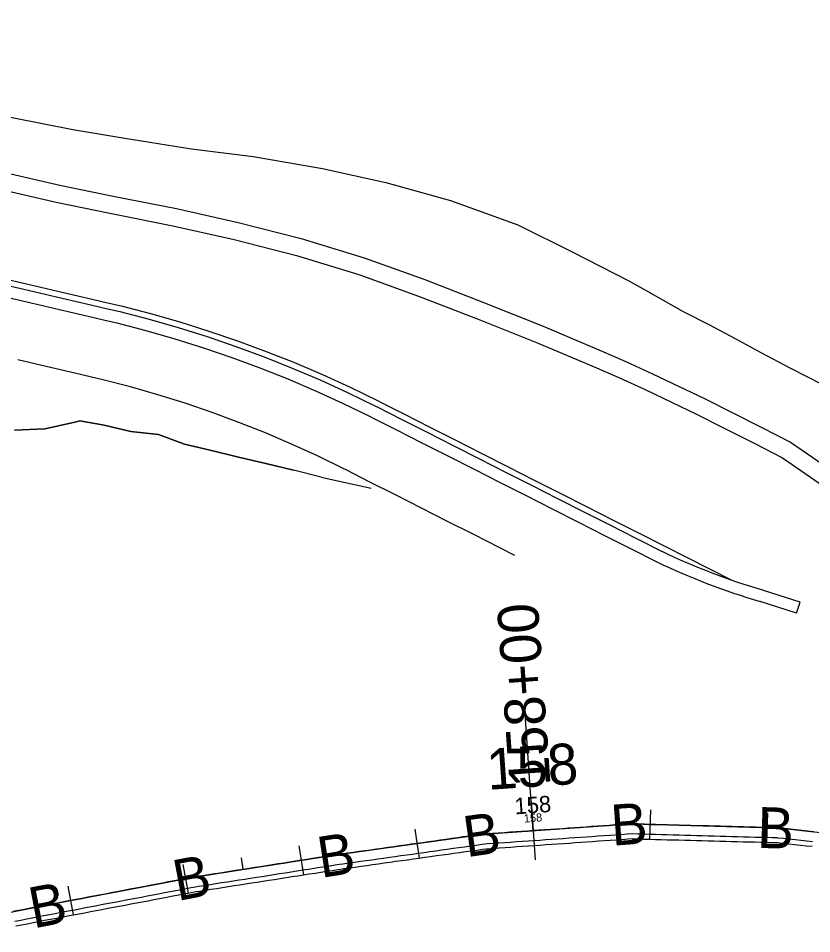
# Model space of a CAD drawing. Extents: x 1823824 to 1861612, y 706975 to 726130.
# Drawn here: x 1825664.3 to 1825799.9, y 715514.9 to 715671.4 of the extents above; entities that cross this region are included whole.
import ezdxf

# ---------------------------------------------------------------- set-up
doc = ezdxf.new("R2010")
doc.units = 0
for name, color, linetype in [('DR_X_Flood_Boundary', 7, 'Continuous'), ('GE_X_CL_10', 7, 'Continuous'), ('GE_X_CL_100', 7, 'Continuous'), ('GE_X_CL_20', 7, 'Continuous'), ('GE_X_CL_200', 7, 'Continuous'), ('GE_X_CL_50', 7, 'Continuous'), ('SC_Scratch1', 7, 'Continuous'), ('SC_Scratch3', 7, 'Continuous'), ('SC_Scratch5', 7, 'Continuous'), ('SC_Scratch6', 7, 'Continuous')]:
    doc.layers.add(name, color=color, linetype=linetype)

msp = doc.modelspace()

# ---------------------------------------------------------------- linework, layer by layer
at = {"layer": 'DR_X_Flood_Boundary'}
for p, q in [((1825743.89, 715531.89), (1825769.06, 715533.64)), ((1825769.06, 715533.64), (1825794.14, 715532.96)), ((1825794.14, 715532.96), (1825817.43, 715530.38)), ((1825718.99, 715528.4), (1825743.89, 715531.89)), ((1825694.33, 715524.53), (1825718.99, 715528.4)), ((1825669.7, 715519.85), (1825694.33, 715524.53)), ((1825643.98, 715514.87), (1825669.7, 715519.85))]:
    msp.add_line(p, q, dxfattribs=at)
at = {"layer": 'GE_X_CL_10'}
for p, q in [((1825752.33, 715532.48), (1825752.26, 715533.47)), ((1825702.79, 715525.86), (1825702.63, 715526.85))]:
    msp.add_line(p, q, dxfattribs=at)
at = {"layer": 'GE_X_CL_100'}
msp.add_line((1825752.33, 715532.48), (1825751.63, 715542.45), dxfattribs=at)
at = {"layer": 'GE_X_CL_20'}
for p, q in [((1825752.33, 715532.48), (1825752.19, 715534.47)), ((1825702.79, 715525.86), (1825702.48, 715527.83))]:
    msp.add_line(p, q, dxfattribs=at)
at = {"layer": 'GE_X_CL_200'}
msp.add_line((1825752.33, 715532.48), (1825750.94, 715552.43), dxfattribs=at)
at = {"layer": 'GE_X_CL_50'}
msp.add_line((1825752.33, 715532.48), (1825751.98, 715537.47), dxfattribs=at)
at = {"layer": 'SC_Scratch1'}
for p, q in [((1825796.3, 715598.91), (1825796.48, 715598.82)), ((1825716.1, 715592.93), (1825724.66, 715591.03)), ((1825774.79, 715581.13), (1825786.13, 715575.37)), ((1825797.93, 715571.57), (1825791.7, 715573.57)), ((1825797.32, 715569.67), (1825791.09, 715571.67)), ((1825797.32, 715569.67), (1825797.93, 715571.57))]:
    msp.add_line(p, q, dxfattribs=at)
for points in [[(1825528.59, 715668.86), (1825540.4, 715670.37), (1825553.63, 715671.36), (1825566.19, 715671.39), (1825577.99, 715670.57), (1825589.44, 715668.99), (1825601.17, 715667.57), (1825612.54, 715665.75), (1825623.77, 715663.16), (1825633.92, 715660.63), (1825643.99, 715658.43), (1825653.89, 715656.38), (1825663.57, 715654.39), (1825673.68, 715652.35), (1825682.56, 715650.87), (1825693.93, 715649.06), (1825704.45, 715647.73), (1825716.32, 715645.7), (1825727.12, 715643.32), (1825738.2, 715640.21), (1825749.67, 715636.1), (1825759.12, 715631.42), (1825768.57, 715626.56), (1825771.61, 715624.85)], [(1825661.6, 715645.14), (1825671.44, 715642.87), (1825680.58, 715640.99), (1825691.37, 715638.84), (1825701.9, 715636.48), (1825712.69, 715633.72), (1825723.46, 715630.42), (1825733.79, 715626.7), (1825744, 715622.72), (1825754.05, 715618.72), (1825763.54, 715614.73), (1825766.46, 715613.43)], [(1825660.92, 715642.22), (1825670.8, 715639.94), (1825679.98, 715638.05), (1825690.75, 715635.9), (1825701.2, 715633.56), (1825711.87, 715630.83), (1825722.52, 715627.58), (1825732.74, 715623.9), (1825742.9, 715619.93), (1825752.91, 715615.95), (1825762.34, 715611.98), (1825765.24, 715610.69)], [(1825662.34, 715626.79), (1825667.21, 715625.65), (1825672.08, 715624.51), (1825676.95, 715623.38), (1825679.6, 715622.75), (1825681.9, 715622.2), (1825686.94, 715620.9), (1825691.94, 715619.47), (1825696.9, 715617.91), (1825701.82, 715616.23), (1825706.7, 715614.43), (1825711.53, 715612.51), (1825716.31, 715610.47), (1825721.04, 715608.31), (1825725.71, 715606.03), (1825726.33, 715605.71), (1825730.2, 715603.75), (1825734.66, 715601.49), (1825739.11, 715599.23), (1825743.57, 715596.97), (1825748.03, 715594.7), (1825752.49, 715592.44), (1825756.95, 715590.18), (1825761.41, 715587.92), (1825765.87, 715585.65), (1825770.33, 715583.39), (1825774.79, 715581.13)], [(1825662.12, 715625.82), (1825666.98, 715624.68), (1825671.85, 715623.54), (1825676.72, 715622.4), (1825679.38, 715621.78), (1825681.67, 715621.23), (1825686.68, 715619.93), (1825691.65, 715618.51), (1825696.59, 715616.96), (1825701.49, 715615.29), (1825706.34, 715613.5), (1825711.15, 715611.58), (1825715.91, 715609.55), (1825720.62, 715607.4), (1825725.26, 715605.13), (1825725.88, 715604.82), (1825729.75, 715602.86), (1825734.21, 715600.6), (1825738.66, 715598.33), (1825743.12, 715596.07), (1825747.58, 715593.81), (1825752.04, 715591.55), (1825756.5, 715589.28), (1825760.96, 715587.02), (1825765.41, 715584.76), (1825769.87, 715582.5), (1825774.33, 715580.24)], [(1825771.61, 715624.85), (1825777.97, 715621.23), (1825782.31, 715619.01), (1825786.84, 715616.63), (1825791.22, 715614.26), (1825796.17, 715611.62), (1825801.88, 715608.7)], [(1825661.66, 715623.87), (1825666.53, 715622.73), (1825671.4, 715621.59), (1825676.27, 715620.45), (1825678.92, 715619.83), (1825681.19, 715619.29), (1825686.15, 715618), (1825691.07, 715616.59), (1825695.96, 715615.06), (1825700.82, 715613.41), (1825705.62, 715611.63), (1825710.38, 715609.74), (1825715.1, 715607.72), (1825719.76, 715605.59), (1825724.36, 715603.35), (1825724.98, 715603.04), (1825728.84, 715601.08), (1825733.3, 715598.82), (1825737.76, 715596.55), (1825742.22, 715594.29), (1825746.67, 715592.03), (1825751.13, 715589.77), (1825755.59, 715587.5), (1825760.05, 715585.24), (1825764.51, 715582.98), (1825768.97, 715580.72), (1825773.43, 715578.45)], [(1825749.19, 715579.54), (1825746.61, 715580.85), (1825742.15, 715583.11), (1825737.69, 715585.37), (1825733.23, 715587.64), (1825728.77, 715589.9), (1825724.31, 715592.16), (1825720.45, 715594.12), (1825719.87, 715594.41), (1825715.49, 715596.55), (1825711.05, 715598.58), (1825706.57, 715600.49), (1825702.04, 715602.29), (1825697.47, 715603.98), (1825692.85, 715605.56), (1825688.2, 715607.01), (1825683.52, 715608.36), (1825678.8, 715609.58), (1825676.64, 715610.1), (1825673.99, 715610.72), (1825669.12, 715611.86), (1825664.25, 715613)], [(1825766.46, 715613.43), (1825768.28, 715612.63), (1825772.7, 715610.62), (1825777.27, 715608.46), (1825781.58, 715606.36), (1825786.18, 715604.05), (1825791.41, 715601.4), (1825796.3, 715598.91)], [(1825765.24, 715610.69), (1825767.05, 715609.89), (1825771.44, 715607.9), (1825775.97, 715605.75), (1825780.25, 715603.68), (1825784.83, 715601.38), (1825790.05, 715598.72), (1825794.94, 715596.24)], [(1825663.69, 715600.98), (1825668.87, 715601.18), (1825674.29, 715602.39), (1825674.88, 715602.54), (1825679, 715601.83), (1825683.57, 715600.75), (1825688.32, 715600.2), (1825692.74, 715598.57), (1825697.35, 715597.47), (1825701.99, 715596.37), (1825706.66, 715595.25), (1825711.37, 715594.13)], [(1825716.1, 715592.93), (1825711.37, 715594.13), (1825706.66, 715595.25), (1825701.99, 715596.37), (1825697.35, 715597.47), (1825692.74, 715598.57), (1825688.32, 715600.2), (1825683.57, 715600.75), (1825679, 715601.83), (1825674.88, 715602.54), (1825674.29, 715602.39), (1825668.87, 715601.18), (1825663.69, 715600.98)], [(1825796.48, 715598.82), (1825811.61, 715588.35), (1825827.84, 715576.05)], [(1825794.94, 715596.24), (1825809.85, 715585.92), (1825826.03, 715573.66)]]:
    msp.add_lwpolyline(points, dxfattribs=at)
for centre, radius, start, end in [((1825785.13, 715575.88), 25.6, 64.1366, 64.2815), ((1825824.98, 715686.31), 117.54, 244.451, 253.5296), ((1825824.98, 715686.31), 119.54, 244.451, 253.5296)]:
    msp.add_arc(centre, radius, start, end, dxfattribs=at)
at = {"layer": 'SC_Scratch3'}
for points in [[(1825800.24, 715532.29), (1825799.25, 715532.4), (1825798.25, 715532.51), (1825797.26, 715532.62), (1825796.27, 715532.73), (1825795.27, 715532.84), (1825794.28, 715532.95), (1825794.14, 715532.97), (1825793.28, 715532.99), (1825792.28, 715533.02), (1825791.28, 715533.04), (1825790.28, 715533.07), (1825789.28, 715533.1), (1825788.28, 715533.13), (1825787.28, 715533.15), (1825786.28, 715533.18), (1825785.28, 715533.21), (1825784.28, 715533.24), (1825783.28, 715533.26), (1825782.28, 715533.29), (1825781.28, 715533.32), (1825780.28, 715533.34), (1825779.28, 715533.37), (1825778.28, 715533.4), (1825777.28, 715533.43), (1825776.28, 715533.45), (1825775.29, 715533.48), (1825774.29, 715533.51), (1825773.29, 715533.54), (1825772.29, 715533.56), (1825771.29, 715533.59), (1825770.29, 715533.62), (1825769.29, 715533.65), (1825769.05, 715533.65), (1825768.29, 715533.6), (1825767.29, 715533.53), (1825766.29, 715533.46), (1825765.3, 715533.39), (1825764.3, 715533.32), (1825763.3, 715533.25), (1825762.3, 715533.18), (1825761.31, 715533.11), (1825760.31, 715533.04), (1825759.31, 715532.97), (1825758.31, 715532.9), (1825757.32, 715532.83), (1825756.32, 715532.77), (1825755.32, 715532.7), (1825754.32, 715532.63), (1825753.32, 715532.56), (1825752.33, 715532.49), (1825751.33, 715532.42), (1825750.33, 715532.35), (1825749.33, 715532.28), (1825748.34, 715532.21), (1825747.34, 715532.14), (1825746.34, 715532.07), (1825745.34, 715532), (1825744.35, 715531.93), (1825743.89, 715531.9), (1825743.35, 715531.82), (1825742.36, 715531.69), (1825741.37, 715531.55), (1825740.38, 715531.41), (1825739.39, 715531.27), (1825738.4, 715531.13), (1825737.41, 715530.99), (1825736.42, 715530.85), (1825735.43, 715530.71), (1825734.44, 715530.57), (1825733.45, 715530.43), (1825732.46, 715530.3), (1825731.47, 715530.16), (1825730.48, 715530.02), (1825729.49, 715529.88), (1825728.5, 715529.74), (1825727.51, 715529.6), (1825726.52, 715529.46), (1825725.53, 715529.32), (1825724.54, 715529.18), (1825723.55, 715529.04), (1825722.56, 715528.91), (1825721.57, 715528.77), (1825720.58, 715528.63), (1825719.59, 715528.49), (1825718.99, 715528.41), (1825718.6, 715528.34), (1825717.61, 715528.19), (1825716.62, 715528.03), (1825715.63, 715527.88), (1825714.64, 715527.72), (1825713.66, 715527.57), (1825712.67, 715527.42), (1825711.68, 715527.26), (1825710.69, 715527.11), (1825709.7, 715526.95), (1825708.72, 715526.8)], [(1825731.47, 715530.17), (1825732.46, 715530.3), (1825733.45, 715530.44), (1825734.44, 715530.58), (1825735.43, 715530.72), (1825736.42, 715530.86), (1825737.41, 715531), (1825738.4, 715531.14), (1825739.39, 715531.28), (1825740.38, 715531.42), (1825741.37, 715531.56), (1825742.36, 715531.69), (1825743.35, 715531.83), (1825743.88, 715531.91), (1825744.35, 715531.94), (1825745.34, 715532.01), (1825746.34, 715532.08), (1825747.34, 715532.15), (1825748.34, 715532.22), (1825749.33, 715532.29), (1825750.33, 715532.36), (1825751.33, 715532.43), (1825752.33, 715532.5), (1825753.32, 715532.57), (1825754.32, 715532.64), (1825755.32, 715532.7), (1825756.32, 715532.77), (1825757.31, 715532.84), (1825758.31, 715532.91), (1825759.31, 715532.98), (1825760.31, 715533.05), (1825761.3, 715533.12), (1825762.3, 715533.19), (1825763.3, 715533.26), (1825764.3, 715533.33), (1825765.3, 715533.4), (1825766.29, 715533.47), (1825767.29, 715533.54), (1825768.29, 715533.61), (1825769.05, 715533.66), (1825769.29, 715533.66), (1825770.29, 715533.63), (1825771.29, 715533.6), (1825772.29, 715533.57), (1825773.29, 715533.55), (1825774.29, 715533.52), (1825775.29, 715533.49), (1825776.29, 715533.46), (1825777.28, 715533.44), (1825778.28, 715533.41), (1825779.28, 715533.38), (1825780.28, 715533.35), (1825781.28, 715533.33), (1825782.28, 715533.3), (1825783.28, 715533.27), (1825784.28, 715533.24), (1825785.28, 715533.22), (1825786.28, 715533.19), (1825787.28, 715533.16), (1825788.28, 715533.13), (1825789.28, 715533.11), (1825790.28, 715533.08), (1825791.28, 715533.05), (1825792.28, 715533.03), (1825793.28, 715533), (1825794.14, 715532.97), (1825794.28, 715532.96), (1825795.27, 715532.85), (1825796.27, 715532.74), (1825797.26, 715532.63), (1825798.25, 715532.52), (1825799.25, 715532.41), (1825800.24, 715532.3)], [(1825799.96, 715529.76), (1825798.97, 715529.86), (1825797.97, 715529.97), (1825796.98, 715530.08), (1825795.99, 715530.19), (1825794.99, 715530.3), (1825794, 715530.4), (1825794.07, 715530.41), (1825793.21, 715530.43), (1825792.21, 715530.45), (1825791.21, 715530.48), (1825790.21, 715530.5), (1825789.21, 715530.53), (1825788.21, 715530.55), (1825787.21, 715530.58), (1825786.21, 715530.6), (1825785.21, 715530.63), (1825784.21, 715530.65), (1825783.21, 715530.68), (1825782.21, 715530.71), (1825781.21, 715530.73), (1825780.21, 715530.76), (1825779.21, 715530.79), (1825778.21, 715530.81), (1825777.21, 715530.84), (1825776.21, 715530.87), (1825775.21, 715530.89), (1825774.21, 715530.92), (1825773.22, 715530.95), (1825772.22, 715530.97), (1825771.22, 715531), (1825770.22, 715531.03), (1825769.22, 715531.06), (1825769.23, 715531.07), (1825768.47, 715531.02), (1825767.47, 715530.95), (1825766.47, 715530.88), (1825765.48, 715530.81), (1825764.48, 715530.74), (1825763.48, 715530.67), (1825762.48, 715530.6), (1825761.49, 715530.53), (1825760.49, 715530.46), (1825759.49, 715530.39), (1825758.49, 715530.32), (1825757.49, 715530.25), (1825756.5, 715530.18), (1825755.5, 715530.11), (1825754.5, 715530.04), (1825753.5, 715529.97), (1825752.51, 715529.91), (1825751.51, 715529.84), (1825750.51, 715529.77), (1825749.51, 715529.7), (1825748.52, 715529.63), (1825747.52, 715529.56), (1825746.52, 715529.49), (1825745.52, 715529.42), (1825744.53, 715529.35), (1825744.25, 715529.34), (1825743.71, 715529.26), (1825742.72, 715529.12), (1825741.73, 715528.99), (1825740.74, 715528.85), (1825739.75, 715528.71), (1825738.76, 715528.57), (1825737.77, 715528.43), (1825736.78, 715528.3), (1825735.79, 715528.16), (1825734.8, 715528.02), (1825733.81, 715527.88), (1825732.82, 715527.74), (1825731.83, 715527.6), (1825730.84, 715527.46), (1825729.85, 715527.33), (1825728.86, 715527.19), (1825727.87, 715527.05), (1825726.88, 715526.91), (1825725.88, 715526.77), (1825724.89, 715526.64), (1825723.9, 715526.5), (1825722.91, 715526.36), (1825721.92, 715526.22), (1825720.93, 715526.08), (1825719.94, 715525.94), (1825719.39, 715525.87), (1825718.99, 715525.81), (1825718, 715525.65), (1825717.02, 715525.5), (1825716.03, 715525.34), (1825715.04, 715525.19), (1825714.05, 715525.04), (1825713.06, 715524.88), (1825712.08, 715524.73), (1825711.09, 715524.57), (1825710.1, 715524.42), (1825709.11, 715524.27)], [(1825731.7, 715528.5), (1825732.69, 715528.64), (1825733.68, 715528.78), (1825734.67, 715528.92), (1825735.66, 715529.06), (1825736.65, 715529.2), (1825737.64, 715529.34), (1825738.63, 715529.48), (1825739.62, 715529.61), (1825740.61, 715529.75), (1825741.6, 715529.89), (1825742.59, 715530.03), (1825743.58, 715530.17), (1825744.12, 715530.25), (1825744.46, 715530.27), (1825745.46, 715530.34), (1825746.46, 715530.4), (1825747.46, 715530.47), (1825748.45, 715530.54), (1825749.45, 715530.61), (1825750.45, 715530.68), (1825751.45, 715530.75), (1825752.44, 715530.82), (1825753.44, 715530.89), (1825754.44, 715530.96), (1825755.44, 715531.03), (1825756.43, 715531.1), (1825757.43, 715531.17), (1825758.43, 715531.24), (1825759.43, 715531.31), (1825760.42, 715531.38), (1825761.42, 715531.45), (1825762.42, 715531.52), (1825763.42, 715531.59), (1825764.41, 715531.66), (1825765.41, 715531.72), (1825766.41, 715531.79), (1825767.41, 715531.86), (1825768.4, 715531.93), (1825769.17, 715531.99), (1825769.24, 715531.98), (1825770.24, 715531.95), (1825771.24, 715531.92), (1825772.24, 715531.89), (1825773.24, 715531.87), (1825774.24, 715531.84), (1825775.24, 715531.81), (1825776.24, 715531.79), (1825777.24, 715531.76), (1825778.24, 715531.73), (1825779.24, 715531.7), (1825780.24, 715531.68), (1825781.24, 715531.65), (1825782.24, 715531.62), (1825783.24, 715531.59), (1825784.24, 715531.57), (1825785.24, 715531.54), (1825786.24, 715531.51), (1825787.24, 715531.48), (1825788.23, 715531.46), (1825789.23, 715531.43), (1825790.23, 715531.4), (1825791.23, 715531.37), (1825792.23, 715531.35), (1825793.23, 715531.32), (1825794.09, 715531.3), (1825794.09, 715531.29), (1825795.09, 715531.18), (1825796.08, 715531.07), (1825797.08, 715530.96), (1825798.07, 715530.85), (1825799.06, 715530.74), (1825800.06, 715530.63)], [(1825663.45, 715518.66), (1825664.43, 715518.85), (1825665.41, 715519.04), (1825666.39, 715519.23), (1825667.37, 715519.42), (1825668.35, 715519.61), (1825669.34, 715519.8), (1825669.69, 715519.87), (1825670.32, 715519.99), (1825671.3, 715520.18), (1825672.28, 715520.36), (1825673.27, 715520.55), (1825674.25, 715520.74), (1825675.23, 715520.92), (1825676.21, 715521.11), (1825677.2, 715521.3), (1825678.18, 715521.48), (1825679.16, 715521.67), (1825680.14, 715521.86), (1825681.13, 715522.04), (1825682.11, 715522.23), (1825683.09, 715522.42), (1825684.07, 715522.6), (1825685.06, 715522.79), (1825686.04, 715522.98), (1825687.02, 715523.16), (1825688, 715523.35), (1825688.98, 715523.54), (1825689.97, 715523.72), (1825690.95, 715523.91), (1825691.93, 715524.1), (1825692.91, 715524.28), (1825693.9, 715524.47), (1825694.32, 715524.55), (1825694.88, 715524.64), (1825695.87, 715524.79), (1825696.86, 715524.95), (1825697.85, 715525.1), (1825698.83, 715525.26), (1825699.82, 715525.41), (1825700.81, 715525.57), (1825701.8, 715525.72), (1825702.79, 715525.88), (1825703.77, 715526.03), (1825704.76, 715526.19), (1825705.75, 715526.34), (1825706.74, 715526.5), (1825707.73, 715526.65), (1825708.71, 715526.81), (1825709.7, 715526.96), (1825710.69, 715527.11), (1825711.68, 715527.27), (1825712.67, 715527.42), (1825713.65, 715527.58), (1825714.64, 715527.73), (1825715.63, 715527.89), (1825716.62, 715528.04), (1825717.61, 715528.2), (1825718.59, 715528.35), (1825718.99, 715528.41), (1825719.58, 715528.5), (1825720.57, 715528.64), (1825721.56, 715528.78), (1825722.55, 715528.91), (1825723.54, 715529.05), (1825724.54, 715529.19), (1825725.53, 715529.33), (1825726.52, 715529.47), (1825727.51, 715529.61), (1825728.5, 715529.75), (1825729.49, 715529.89), (1825730.48, 715530.03), (1825731.47, 715530.17)], [(1825663.77, 715517.01), (1825664.75, 715517.2), (1825665.73, 715517.4), (1825666.71, 715517.59), (1825667.69, 715517.78), (1825668.67, 715517.97), (1825669.66, 715518.16), (1825670.01, 715518.22), (1825670.63, 715518.34), (1825671.61, 715518.53), (1825672.6, 715518.72), (1825673.58, 715518.9), (1825674.56, 715519.09), (1825675.54, 715519.28), (1825676.53, 715519.46), (1825677.51, 715519.65), (1825678.49, 715519.84), (1825679.47, 715520.02), (1825680.46, 715520.21), (1825681.44, 715520.4), (1825682.42, 715520.58), (1825683.4, 715520.77), (1825684.39, 715520.96), (1825685.37, 715521.14), (1825686.35, 715521.33), (1825687.33, 715521.52), (1825688.32, 715521.7), (1825689.3, 715521.89), (1825690.28, 715522.08), (1825691.26, 715522.26), (1825692.25, 715522.45), (1825693.23, 715522.64), (1825694.21, 715522.82), (1825694.64, 715522.9), (1825695.14, 715522.98), (1825696.13, 715523.14), (1825697.12, 715523.29), (1825698.11, 715523.45), (1825699.09, 715523.6), (1825700.08, 715523.75), (1825701.07, 715523.91), (1825702.06, 715524.06), (1825703.05, 715524.22), (1825704.03, 715524.37), (1825705.02, 715524.53), (1825706.01, 715524.68), (1825707, 715524.84), (1825707.99, 715524.99), (1825708.97, 715525.15), (1825709.96, 715525.3), (1825710.95, 715525.46), (1825711.94, 715525.61), (1825712.93, 715525.77), (1825713.91, 715525.92), (1825714.9, 715526.08), (1825715.89, 715526.23), (1825716.88, 715526.38), (1825717.87, 715526.54), (1825718.85, 715526.69), (1825719.25, 715526.76), (1825719.82, 715526.84), (1825720.81, 715526.97), (1825721.8, 715527.11), (1825722.79, 715527.25), (1825723.78, 715527.39), (1825724.77, 715527.53), (1825725.76, 715527.67), (1825726.75, 715527.81), (1825727.74, 715527.95), (1825728.73, 715528.09), (1825729.72, 715528.23), (1825730.71, 715528.36), (1825731.7, 715528.5)], [(1825708.72, 715526.8), (1825707.73, 715526.64), (1825706.74, 715526.49), (1825705.75, 715526.33), (1825704.76, 715526.18), (1825703.78, 715526.02), (1825702.79, 715525.87), (1825701.8, 715525.71), (1825700.81, 715525.56), (1825699.82, 715525.4), (1825698.84, 715525.25), (1825697.85, 715525.1), (1825696.86, 715524.94), (1825695.87, 715524.79), (1825694.88, 715524.63), (1825694.32, 715524.54), (1825693.9, 715524.46), (1825692.92, 715524.28), (1825691.93, 715524.09), (1825690.95, 715523.9), (1825689.97, 715523.72), (1825688.99, 715523.53), (1825688, 715523.34), (1825687.02, 715523.16), (1825686.04, 715522.97), (1825685.06, 715522.78), (1825684.07, 715522.6), (1825683.09, 715522.41), (1825682.11, 715522.22), (1825681.13, 715522.04), (1825680.14, 715521.85), (1825679.16, 715521.66), (1825678.18, 715521.48), (1825677.2, 715521.29), (1825676.21, 715521.1), (1825675.23, 715520.92), (1825674.25, 715520.73), (1825673.27, 715520.54), (1825672.29, 715520.36), (1825671.3, 715520.17), (1825670.32, 715519.98), (1825669.7, 715519.86), (1825669.34, 715519.8), (1825668.36, 715519.6), (1825667.37, 715519.41), (1825666.39, 715519.22), (1825665.41, 715519.03), (1825664.43, 715518.84), (1825663.45, 715518.65)], [(1825709.11, 715524.27), (1825708.12, 715524.11), (1825707.14, 715523.96), (1825706.15, 715523.81), (1825705.16, 715523.65), (1825704.17, 715523.5), (1825703.18, 715523.34), (1825702.2, 715523.19), (1825701.21, 715523.04), (1825700.22, 715522.88), (1825699.23, 715522.73), (1825698.24, 715522.57), (1825697.26, 715522.42), (1825696.27, 715522.26), (1825695.28, 715522.11), (1825694.8, 715522.04), (1825694.38, 715521.95), (1825693.39, 715521.77), (1825692.41, 715521.58), (1825691.43, 715521.39), (1825690.45, 715521.21), (1825689.46, 715521.02), (1825688.48, 715520.84), (1825687.5, 715520.65), (1825686.52, 715520.46), (1825685.53, 715520.28), (1825684.55, 715520.09), (1825683.57, 715519.9), (1825682.59, 715519.72), (1825681.6, 715519.53), (1825680.62, 715519.34), (1825679.64, 715519.16), (1825678.66, 715518.97), (1825677.67, 715518.79), (1825676.69, 715518.6), (1825675.71, 715518.41), (1825674.73, 715518.23), (1825673.74, 715518.04), (1825672.76, 715517.85), (1825671.78, 715517.67), (1825670.8, 715517.48), (1825670.18, 715517.36), (1825669.82, 715517.3), (1825668.84, 715517.11), (1825667.86, 715516.91), (1825666.88, 715516.72), (1825665.9, 715516.53), (1825664.91, 715516.34), (1825663.93, 715516.15)]]:
    msp.add_lwpolyline(points, dxfattribs=at)
at = {"layer": 'SC_Scratch5'}
for points in [[(1825751.98, 715537.47), (1825752.68, 715527.49)], [(1825772.35, 715536.05), (1825772.22, 715531.05)], [(1825792.35, 715535.51), (1825792.21, 715530.51)], [(1825732.11, 715532.76), (1825732.81, 715527.81)], [(1825712.28, 715529.88), (1825713.06, 715524.94)], [(1825692.45, 715526.72), (1825693.38, 715521.81)], [(1825672.8, 715522.99), (1825673.74, 715518.08)]]:
    msp.add_lwpolyline(points, dxfattribs=at)

# ---------------------------------------------------------------- texts
at = {"layer": 'GE_X_CL_10'}
msp.add_text('158', height=1.4, rotation=3.9843, dxfattribs=at).set_placement((1825750.78, 715533.87))
at = {"layer": 'GE_X_CL_20'}
msp.add_text('158', height=2.8, rotation=3.9843, dxfattribs=at).set_placement((1825749.24, 715535.27))
at = {"layer": 'GE_X_CL_50'}
msp.add_text('158', height=7, rotation=3.9843, dxfattribs=at).set_placement((1825744.61, 715539.46))
at = {"layer": 'SC_Scratch5'}
msp.add_text('158+00', height=7, rotation=93.9843, dxfattribs=at).set_placement((1825755.3, 715540.2))
at = {"layer": 'SC_Scratch6'}
for rotation, p in [(3.9843, (1825765.81, 715529.91)), (7.9886, (1825740.91, 715527.94)), (358.4311, (1825790.54, 715529.55)), (8.8994, (1825716.07, 715524.4)), (10.7568, (1825691.54, 715520.44)), (10.9595, (1825666.93, 715515.75))]:
    msp.add_text('B', height=7, rotation=rotation, dxfattribs=at).set_placement(p)

doc.saveas('drawing.dxf')
